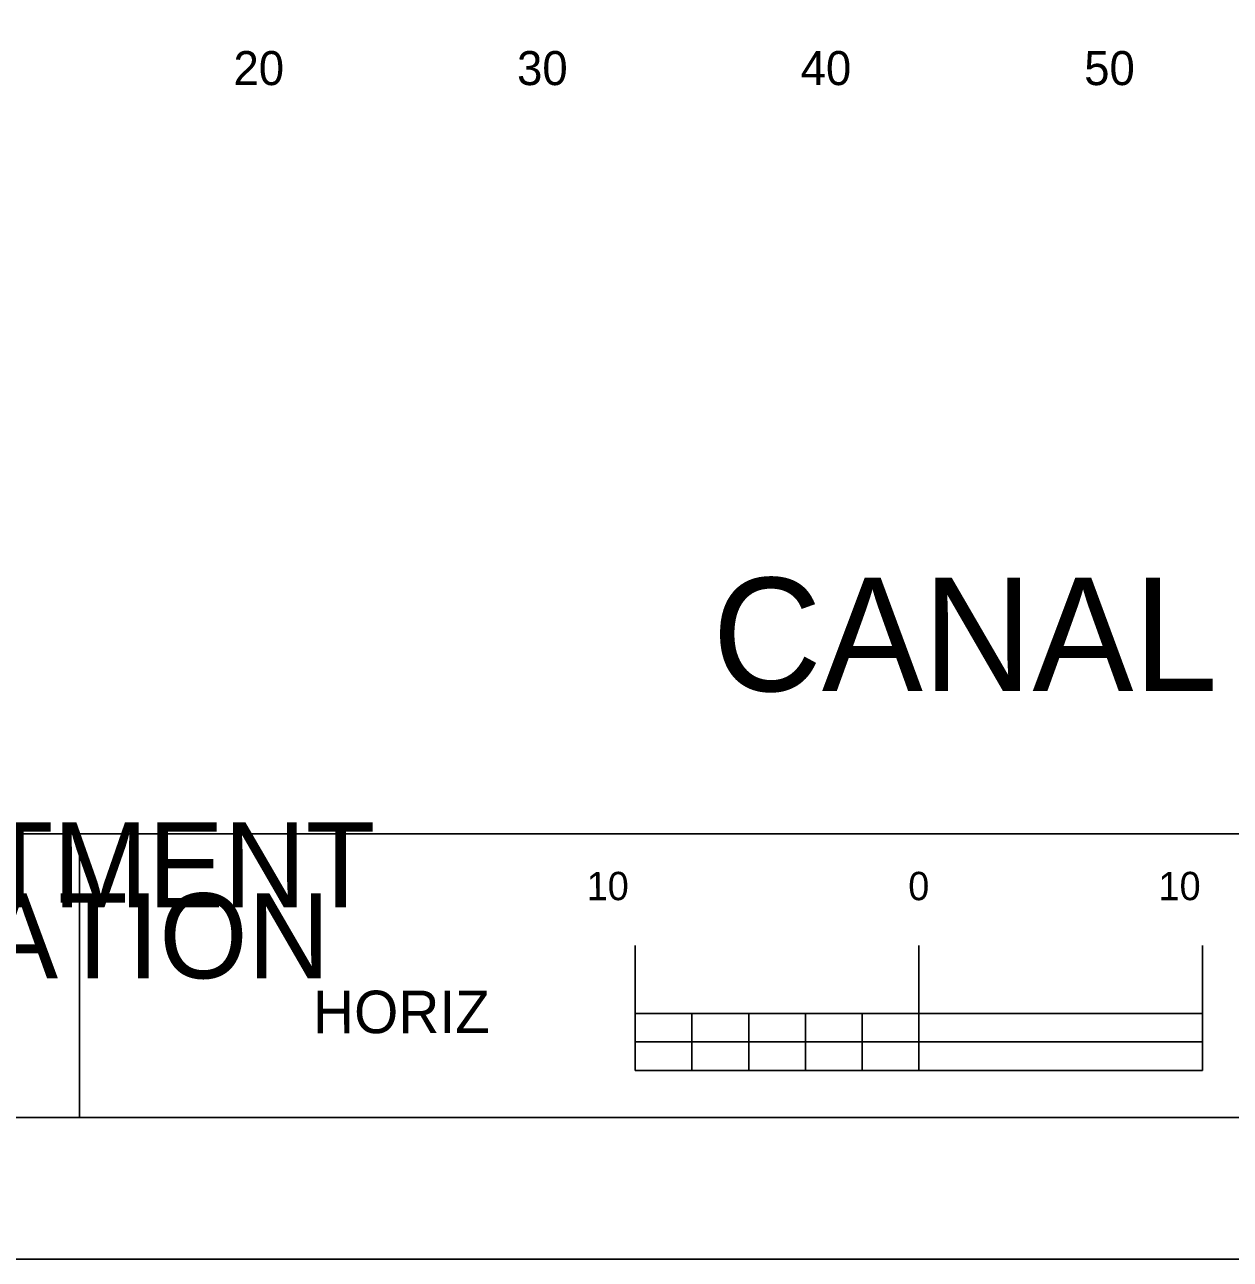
# Model space of a CAD drawing. Extents: x 2193008 to 2198143, y 1236112 to 1237864.
# Drawn here: x 2194739.22 to 2194781.74, y 1237118.04 to 1237161.58 of the extents above; entities that cross this region are included whole.
import ezdxf

# ---------------------------------------------------------------- set-up
doc = ezdxf.new("R2010")
doc.units = 0
for name, color, linetype in [('10', 7, 'Continuous'), ('ANNO-SYMB', 7, 'Continuous'), ('ANNO-TXT', 7, 'Continuous'), ('Level 33', 7, 'Continuous'), ('Level 62', 7, 'Continuous'), ('SHT-BDR', 7, 'Continuous'), ('SHT-BNDRY', 7, 'Continuous')]:
    doc.layers.add(name, color=color, linetype=linetype)

msp = doc.modelspace()

# ---------------------------------------------------------------- linework, layer by layer
at = {"layer": 'ANNO-SYMB'}
for p, q in [((2194760.755, 1237124.7), (2194760.755, 1237129.1)), ((2194770.755, 1237124.7), (2194770.755, 1237129.1)), ((2194770.755, 1237124.7), (2194770.755, 1237129.1)), ((2194770.755, 1237124.7), (2194770.755, 1237129.1)), ((2194780.755, 1237124.7), (2194780.755, 1237129.1)), ((2194780.755, 1237126.7), (2194760.755, 1237126.7)), ((2194762.755, 1237125.7), (2194762.755, 1237126.7)), ((2194762.755, 1237125.7), (2194762.755, 1237126.7)), ((2194770.755, 1237125.7), (2194770.755, 1237126.7)), ((2194770.755, 1237125.7), (2194770.755, 1237126.7)), ((2194770.755, 1237125.7), (2194770.755, 1237126.7)), ((2194770.755, 1237125.7), (2194766.755, 1237125.7)), ((2194780.755, 1237124.7), (2194780.755, 1237125.7)), ((2194780.755, 1237124.7), (2194780.755, 1237125.7)), ((2194780.755, 1237124.7), (2194780.755, 1237125.7)), ((2194780.755, 1237124.7), (2194760.755, 1237124.7))]:
    msp.add_line(p, q, dxfattribs=at)
for points in [[(2194760.755, 1237126.7), (2194762.755, 1237126.7), (2194762.755, 1237125.7), (2194760.755, 1237125.7)], [(2194764.755, 1237126.7), (2194766.755, 1237126.7), (2194766.755, 1237125.7), (2194764.755, 1237125.7)], [(2194768.755, 1237126.7), (2194770.755, 1237126.7), (2194770.755, 1237125.7), (2194768.755, 1237125.7)], [(2194762.755, 1237125.7), (2194764.755, 1237125.7), (2194764.755, 1237124.7), (2194762.755, 1237124.7)], [(2194766.755, 1237125.7), (2194768.755, 1237125.7), (2194768.755, 1237124.7), (2194766.755, 1237124.7)], [(2194770.755, 1237125.7), (2194780.755, 1237125.7), (2194780.755, 1237124.7), (2194770.755, 1237124.7)]]:
    msp.add_lwpolyline(points, close=True, dxfattribs=at)
at = {"layer": 'Level 62'}
msp.add_lwpolyline([(2194512.691, 1237118.036), (2194852.691, 1237118.036), (2194852.691, 1237338.036), (2194512.691, 1237338.036)], close=True, dxfattribs=at)
at = {"layer": 'SHT-BDR'}
msp.add_lwpolyline([(2194537.688, 1237133.046), (2194837.688, 1237133.046), (2194837.688, 1237323.046), (2194537.688, 1237323.046)], close=True, dxfattribs=at)
at = {"layer": 'SHT-BNDRY'}
msp.add_line((2194741.16, 1237123.036), (2194741.16, 1237133.046), dxfattribs=at)
msp.add_lwpolyline([(2194525.191, 1237123.036), (2194847.691, 1237123.036), (2194847.691, 1237333.036), (2194525.191, 1237333.036)], close=True, dxfattribs=at)

# ---------------------------------------------------------------- texts
at = {"layer": '10'}
for s, p in [('20', (2194746.587, 1237159.446)), ('30', (2194756.587, 1237159.446)), ('40', (2194766.587, 1237159.446)), ('50', (2194776.587, 1237159.446))]:
    msp.add_text(s, height=1.2, dxfattribs=at).set_placement(p)
at = {"layer": 'ANNO-SYMB'}
for s, height, p in [(' 10', 0.9991, (2194758.67, 1237130.7)), ('0', 1, (2194770.382, 1237130.7)), ('0', 1, (2194770.382, 1237130.7)), ('0', 1, (2194770.382, 1237130.7)), (' 10', 0.9991, (2194778.837, 1237130.7)), ('HORIZ', 1.4994, (2194749.393, 1237126.008))]:
    msp.add_text(s, height=height, rotation=0.0572, dxfattribs=at).set_placement(p)
at = {"layer": 'ANNO-TXT'}
for s, p in [('ALABAMA DEPARTMENT', (2194703.889, 1237130.446)), ('OF TRANSPORTATION', (2194706.301, 1237127.946))]:
    msp.add_text(s, height=3, rotation=360, dxfattribs=at).set_placement(p)
at = {"layer": 'Level 33'}
msp.add_text('CANAL ST', height=3.9977, rotation=360, dxfattribs=at).set_placement((2194763.473, 1237138.073))

doc.saveas('drawing.dxf')
